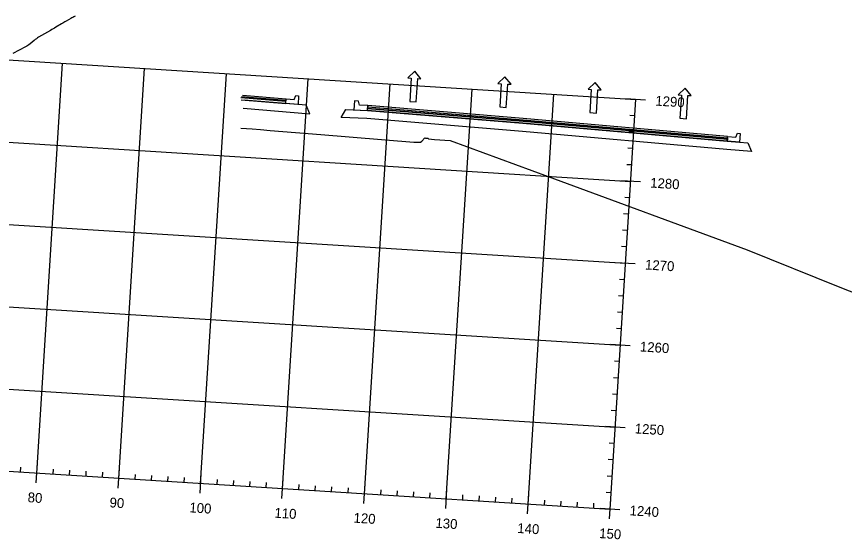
# Model space of a CAD drawing. Extents: x 658976 to 668726, y 639543 to 647196.
# Drawn here: x 662757 to 663261, y 641740 to 642059 of the extents above; entities that cross this region are included whole.
import ezdxf

# ---------------------------------------------------------------- set-up
doc = ezdxf.new("R2010")
doc.units = 0
for name, color, linetype in [('Ex_Minor Contours', 7, 'Continuous'), ('R_Axis', 7, 'Continuous'), ('R_Axis Annot', 7, 'Continuous'), ('R_Exist Surface', 7, 'Continuous'), ('R_Fin Surface', 7, 'Continuous'), ('R_Grid', 7, 'Continuous'), ('R_MOT', 7, 'Continuous'), ('R_Proposed Const Limits', 7, 'Continuous'), ('R_Sub Surface', 7, 'Continuous')]:
    doc.layers.add(name, color=color, linetype=linetype)

msp = doc.modelspace()

# ---------------------------------------------------------------- linework, layer by layer
for points in [[(662921.01, 642008.54), (662926, 642008.12), (662926.98, 642010.57), (662928.65, 642010.46), (662928.31, 642005.01), (662920.83, 642005.63)], [(662970.85, 642004.41), (662965.86, 642004.62), (662965.18, 642007.17), (662962.69, 642007.32), (662962.34, 642001.85), (662970.67, 642001.5)], [(663190.11, 641985.6), (663195.09, 641985.18), (663196.08, 641987.63), (663197.74, 641987.52), (663197.4, 641982.07), (663189.92, 641982.69)]]:
    msp.add_lwpolyline(points, close=True)
at = {"layer": 'Ex_Minor Contours'}
msp.add_lwpolyline([(662792.4, 642058.88), (662791.76, 642058.51), (662791.13, 642058.15), (662790.5, 642057.78), (662789.86, 642057.41), (662786.98, 642055.75), (662786.29, 642055.35), (662785.6, 642054.95), (662784.91, 642054.55), (662784.22, 642054.14), (662780.74, 642052.11), (662779.93, 642051.64), (662779.12, 642051.17), (662778.31, 642050.7), (662777.5, 642050.23), (662770.24, 642046.01), (662769.54, 642045.58), (662768.85, 642045.12), (662768.18, 642044.64), (662767.53, 642044.13), (662764.98, 642042.02), (662764.33, 642041.51), (662763.66, 642041.04), (662762.97, 642040.6), (662762.25, 642040.19), (662754.58, 642036.1)], dxfattribs=at)
at = {"layer": 'R_Axis'}
for p, q in [((663118.48, 641758.67), (663134.15, 642008.18)), ((663140.14, 642007.8), (663128.16, 642008.55)), ((663133.52, 641998.2), (663130.53, 641998.38)), ((663132.9, 641988.22), (663129.9, 641988.4)), ((663132.27, 641978.23), (663129.28, 641978.42)), ((663131.64, 641968.25), (663128.65, 641968.44)), ((663137, 641957.9), (663125.03, 641958.65)), ((663130.39, 641948.29), (663127.4, 641948.48)), ((663129.76, 641938.31), (663126.77, 641938.5)), ((663129.14, 641928.33), (663126.14, 641928.52)), ((663128.51, 641918.35), (663125.52, 641918.54)), ((663133.87, 641908), (663121.89, 641908.75)), ((663127.26, 641898.39), (663124.26, 641898.58)), ((663126.63, 641888.41), (663123.63, 641888.6)), ((663126, 641878.43), (663123.01, 641878.62)), ((663125.38, 641868.45), (663122.38, 641868.64)), ((663130.74, 641858.09), (663118.76, 641858.85)), ((661621.43, 641852.69), (663118.48, 641758.67)), ((663124.12, 641848.49), (663121.13, 641848.68)), ((663123.49, 641838.51), (663120.5, 641838.7)), ((663122.87, 641828.53), (663119.87, 641828.72)), ((663122.24, 641818.55), (663119.25, 641818.74)), ((663127.6, 641808.19), (663115.63, 641808.95)), ((663120.99, 641798.59), (663117.99, 641798.78)), ((663120.36, 641788.61), (663117.37, 641788.8)), ((662759.19, 641781.23), (662759.38, 641784.23)), ((662768.79, 641774.62), (662769.54, 641786.59)), ((662779.15, 641779.98), (662779.34, 641782.97)), ((662789.13, 641779.35), (662789.32, 641782.35)), ((662799.11, 641778.73), (662799.3, 641781.72)), ((662809.09, 641778.1), (662809.28, 641781.09)), ((662818.69, 641771.48), (662819.45, 641783.46)), ((662829.05, 641776.84), (662829.24, 641779.84)), ((662839.03, 641776.22), (662839.22, 641779.21)), ((662849.01, 641775.59), (662849.2, 641778.59)), ((662868.6, 641768.35), (662869.35, 641780.33)), ((663119.73, 641778.63), (663116.74, 641778.82)), ((662858.99, 641774.96), (662859.18, 641777.96)), ((662878.95, 641773.71), (662879.14, 641776.7)), ((662888.93, 641773.08), (662889.12, 641776.08)), ((662898.91, 641772.46), (662899.1, 641775.45)), ((662908.89, 641771.83), (662909.08, 641774.82)), ((662918.5, 641765.22), (662919.25, 641777.19)), ((662928.85, 641770.58), (662929.04, 641773.57)), ((662968.4, 641762.08), (662969.15, 641774.06)), ((662938.83, 641769.95), (662939.02, 641772.94)), ((662948.81, 641769.32), (662949, 641772.32)), ((662958.79, 641768.7), (662958.98, 641771.69)), ((662978.76, 641767.44), (662978.94, 641770.44)), ((662988.74, 641766.82), (662988.92, 641769.81)), ((662998.72, 641766.19), (662998.9, 641769.18)), ((663008.7, 641765.56), (663008.88, 641768.56)), ((663018.3, 641758.95), (663019.05, 641770.92)), ((663119.11, 641768.65), (663116.11, 641768.84)), ((663028.66, 641764.31), (663028.85, 641767.3)), ((663038.64, 641763.68), (663038.83, 641766.68)), ((663048.62, 641763.06), (663048.81, 641766.05)), ((663058.6, 641762.43), (663058.79, 641765.42)), ((663068.2, 641755.81), (663068.95, 641767.79)), ((663078.56, 641761.17), (663078.75, 641764.17)), ((663088.54, 641760.55), (663088.73, 641763.54)), ((663118.1, 641752.68), (663118.86, 641764.66)), ((663098.52, 641759.92), (663098.71, 641762.92)), ((663108.5, 641759.29), (663108.69, 641762.29)), ((663124.47, 641758.29), (663112.49, 641759.04))]:
    msp.add_line(p, q, dxfattribs=at)
at = {"layer": 'R_Exist Surface'}
msp.add_lwpolyline([(662893.39, 641990.76), (662900.41, 641990.19), (662905.36, 641989.78), (662911.28, 641989.29), (662942.23, 641986.75), (662998.84, 641982.05), (663001.56, 641982.07), (663003.04, 641982.08), (663003.72, 641982.78), (663005.66, 641984.69), (663006.07, 641984.67), (663007.09, 641984.67), (663007.33, 641984.58), (663007.89, 641984.18), (663011.44, 641983.84), (663021.03, 641983.09), (663080.69, 641961.18), (663201.95, 641916.49), (663257.54, 641894.3), (663303.43, 641876.09)], dxfattribs=at)
at = {"layer": 'R_Fin Surface'}
msp.add_lwpolyline([(662893.67, 642007.88), (662920.83, 642005.63), (662920.91, 642006.88), (662893.39, 642009.16)], dxfattribs=at)
for points in [[(662970.75, 642002.74), (663065.44, 641994.89), (663190, 641983.93), (663189.92, 641982.69), (663065.36, 641993.65), (662970.67, 642001.5)], [(662970.8, 642003.57), (663065.49, 641995.72), (663190.05, 641984.77), (663190, 641983.93), (663065.44, 641994.89), (662970.75, 642002.74)]]:
    msp.add_lwpolyline(points, close=True, dxfattribs=at)
at = {"layer": 'R_Grid'}
for p, q in [((661637.1, 642102.2), (663134.15, 642008.18)), ((661633.97, 642052.3), (663131.02, 641958.27)), ((662769.17, 641780.61), (662784.84, 642030.11)), ((662819.07, 641777.47), (662834.74, 642026.98)), ((662868.97, 641774.34), (662884.64, 642023.85)), ((662918.87, 641771.2), (662934.54, 642020.71)), ((662968.78, 641768.07), (662984.45, 642017.58)), ((663018.68, 641764.94), (663034.35, 642014.44)), ((663068.58, 641761.8), (663084.25, 642011.31)), ((663118.48, 641758.67), (663134.15, 642008.18)), ((661630.83, 642002.39), (663127.88, 641908.37)), ((661627.7, 641952.49), (663124.75, 641858.47)), ((661624.56, 641902.59), (663121.61, 641808.57)), ((661621.43, 641852.69), (663118.48, 641758.67))]:
    msp.add_line(p, q, dxfattribs=at)
at = {"layer": 'R_MOT'}
for p, q in [((662999.53, 642025.44), (662995.26, 642021.32)), ((662995.26, 642021.32), (662997.26, 642021.19)), ((662997.26, 642021.19), (662996.37, 642007.01)), ((663003.25, 642020.81), (662999.53, 642025.44)), ((663000.36, 642006.76), (663001.25, 642020.94)), ((663001.25, 642020.94), (663003.25, 642020.81)), ((663054.42, 642022), (663050.15, 642017.87)), ((663058.14, 642017.37), (663054.42, 642022)), ((663050.15, 642017.87), (663052.15, 642017.74)), ((663052.15, 642017.74), (663051.26, 642003.57)), ((663055.25, 642003.32), (663056.14, 642017.49)), ((663056.14, 642017.49), (663058.14, 642017.37)), ((663109.31, 642018.55), (663105.05, 642014.42)), ((663113.03, 642013.92), (663109.31, 642018.55)), ((663105.05, 642014.42), (663107.04, 642014.3)), ((663107.04, 642014.3), (663106.15, 642000.12)), ((663110.14, 641999.87), (663111.03, 642014.04)), ((663111.03, 642014.04), (663113.03, 642013.92)), ((663164.2, 642015.1), (663159.94, 642010.97)), ((663159.94, 642010.97), (663161.93, 642010.85)), ((663161.93, 642010.85), (663161.04, 641996.67)), ((663167.92, 642010.47), (663164.2, 642015.1)), ((663165.03, 641996.42), (663165.93, 642010.6)), ((663165.93, 642010.6), (663167.92, 642010.47)), ((662996.37, 642007.01), (663000.36, 642006.76)), ((663051.26, 642003.57), (663055.25, 642003.32)), ((663106.15, 642000.12), (663110.14, 641999.87)), ((663161.04, 641996.67), (663165.03, 641996.42))]:
    msp.add_line(p, q, dxfattribs=at)
at = {"layer": 'R_Proposed Const Limits'}
for p, q in [((662894.56, 642010.73), (662921.01, 642008.54)), ((662893.79, 642009.96), (662920.96, 642007.7)), ((662921.01, 642008.54), (662920.96, 642007.7))]:
    msp.add_line(p, q, dxfattribs=at)
msp.add_lwpolyline([(663190.05, 641984.77), (663190.11, 641985.6), (663065.55, 641996.56), (662970.85, 642004.41), (662970.8, 642003.57), (663065.49, 641995.72)], close=True, dxfattribs=at)
at = {"layer": 'R_Sub Surface'}
msp.add_lwpolyline([(662894.93, 642002.76), (662935.49, 641999.4), (662933.29, 642004.6), (662895.44, 642007.73)], dxfattribs=at)
msp.add_lwpolyline([(662970.67, 642001.5), (663065.36, 641993.65), (663189.92, 641982.69), (663197.4, 641982.07), (663202.38, 641981.65), (663204.58, 641976.46), (663189.61, 641977.7), (663065.05, 641988.65), (662970.34, 641996.51), (662954.51, 641997.18), (662957.35, 642002.06)], close=True, dxfattribs=at)

# ---------------------------------------------------------------- texts
at = {"layer": 'R_Axis Annot'}
for s, p in [('1290', (663145.94, 642004.43)), ('1280', (663142.8, 641954.53)), ('1270', (663139.67, 641904.63)), ('1260', (663136.54, 641854.72)), ('1250', (663133.4, 641804.82)), ('80', (662763.4, 641762.93)), ('90', (662813.3, 641759.8)), ('100', (662861.97, 641756.74)), ('110', (662913.81, 641753.49)), ('1240', (663130.27, 641754.92)), ('120', (662962.01, 641750.46)), ('130', (663011.92, 641747.32)), ('140', (663061.82, 641744.19)), ('150', (663111.72, 641741.06))]:
    msp.add_text(s, height=6, rotation=356.4063, dxfattribs=at).set_placement(p)

doc.saveas('drawing.dxf')
